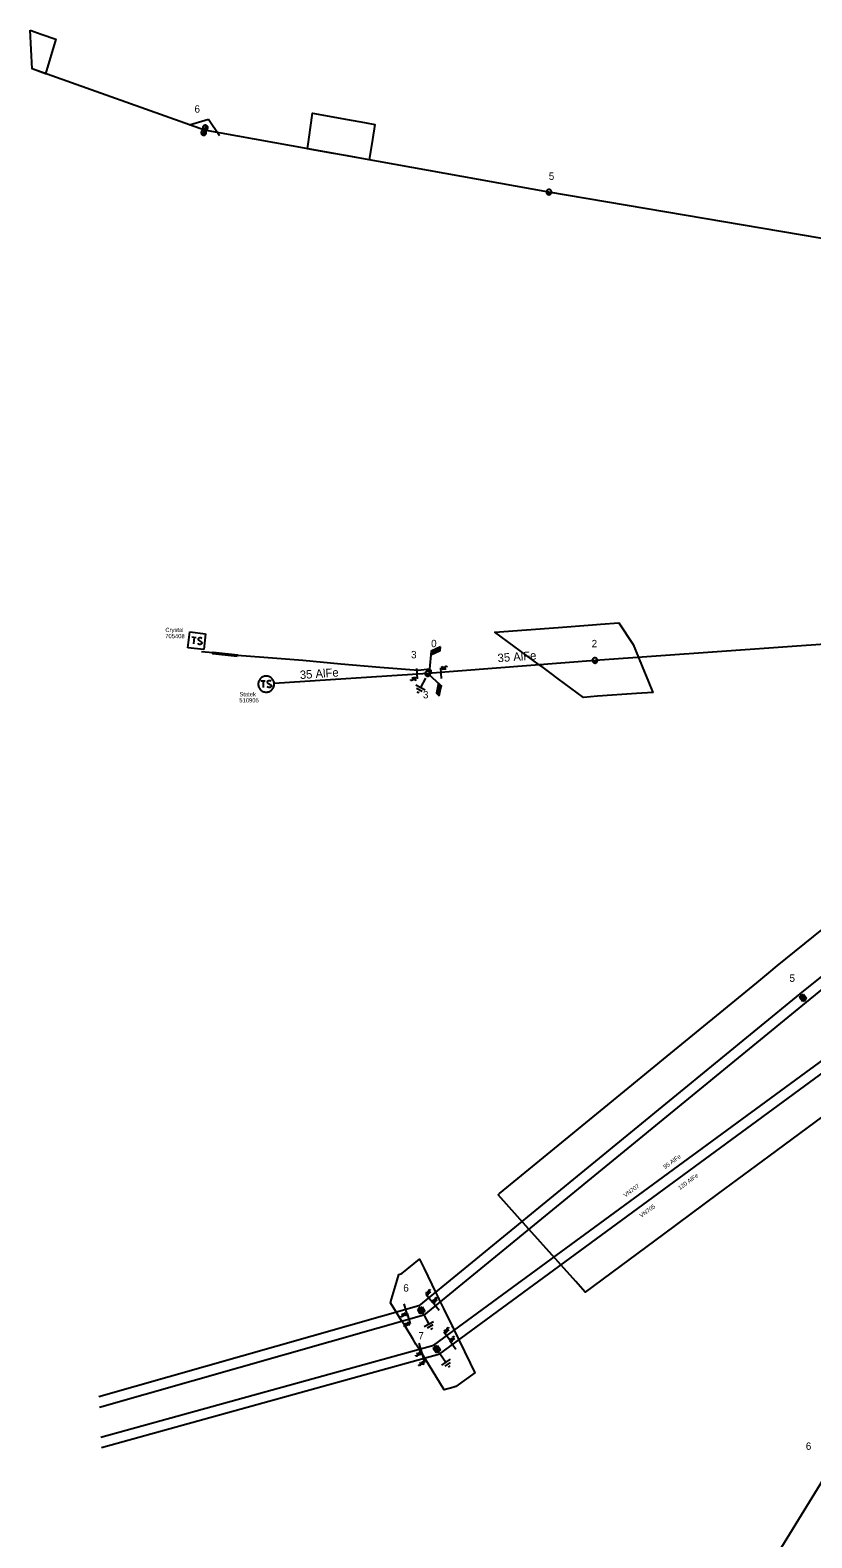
# Model space of a CAD drawing. Extents: x -545588 to -543214, y -1196037 to -1194452.
# Drawn here: x -545587.8 to -545402.3, y -1195194.1 to -1194836.6 of the extents above; entities that cross this region are included whole.
import ezdxf

# ---------------------------------------------------------------- set-up
doc = ezdxf.new("R2010")
doc.units = 0
for name, color, linetype in [('DOPLŇ_POPISY', 7, 'Continuous'), ('ELE_EON', 7, 'Continuous'), ('ELE_EON_POPIS', 7, 'Continuous'), ('Implicitní', 7, 'Continuous'), ('KONEC_VEDENÍ', 7, 'Continuous'), ('POL_ZNAČKA_PRACOVNÍ', 7, 'Continuous'), ('SDEL_EON', 7, 'Continuous'), ('TECH_OCHR_PÁSMO_HRAN', 7, 'Continuous'), ('Vrstva 18', 7, 'Continuous'), ('Vrstva 20', 7, 'Continuous'), ('Vrstva 25', 7, 'Continuous'), ('Vrstva 26', 7, 'Continuous'), ('Vrstva 27', 7, 'Continuous'), ('Vrstva 35', 7, 'Continuous'), ('Vrstva 52', 7, 'Continuous'), ('Vrstva 53', 7, 'Continuous'), ('ZP_EON', 7, 'Continuous'), ('ZP_EON_POPIS', 7, 'Continuous')]:
    doc.layers.add(name, color=color, linetype=linetype)

# ---------------------------------------------------------------- blocks, each defined once
blk = doc.blocks.new('VN840')
at = {"layer": 'POL_ZNAČKA_PRACOVNÍ'}
for points in [[(-0.01, 1.41), (-0.01, -1.09)], [(-1.51, -1.24), (-1.51, -1.15)], [(-1.48, -1.35), (-1.51, -1.24)], [(-1.33, -1.42), (-1.48, -1.35)], [(-1.27, -1.42), (-1.33, -1.42)], [(-1.13, -1.35), (-1.27, -1.42)], [(-1.09, -1.24), (-1.13, -1.35)], [(-1.09, -0.59), (-1.09, -1.24)], [(-0.68, -0.59), (-0.68, -1.42)], [(-0.68, -1.11), (-0.27, -0.59)], [(-0.54, -0.94), (-0.2, -1.42)]]:
    blk.add_lwpolyline(points, dxfattribs=at)
blk = doc.blocks.new('VN860')
at = {"layer": 'POL_ZNAČKA_PRACOVNÍ'}
for points in [[(-3.74, 0), (0.01, 2.82)], [(0.01, 2.82), (3.76, 0)]]:
    blk.add_lwpolyline(points, dxfattribs=at)
blk = doc.blocks.new('VN440')
at = {"layer": 'ELE_EON_POPIS'}
for points in [[(1.22, 0), (1.21, 0.13), (1.19, 0.25), (1.16, 0.38), (1.11, 0.5), (1.05, 0.61), (0.98, 0.72), (0.9, 0.82), (0.81, 0.91), (0.71, 0.99), (0.6, 1.06), (0.49, 1.12), (0.37, 1.16), (0.25, 1.2), (0.12, 1.22), (-0.01, 1.22), (-0.14, 1.22), (-0.26, 1.2), (-0.39, 1.16), (-0.51, 1.12), (-0.62, 1.06), (-0.73, 0.99), (-0.83, 0.91), (-0.92, 0.82), (-1, 0.72), (-1.07, 0.61), (-1.13, 0.5), (-1.18, 0.38), (-1.21, 0.25), (-1.23, 0.13), (-1.24, 0), (-1.23, -0.13), (-1.21, -0.26), (-1.18, -0.38), (-1.13, -0.5), (-1.07, -0.62), (-1, -0.73), (-0.92, -0.83), (-0.83, -0.92), (-0.73, -1), (-0.62, -1.07), (-0.51, -1.13), (-0.39, -1.17), (-0.26, -1.2), (-0.14, -1.23), (-0.01, -1.23), (0.12, -1.23), (0.25, -1.2), (0.37, -1.17), (0.49, -1.13), (0.6, -1.07), (0.71, -1), (0.81, -0.92), (0.9, -0.83), (0.98, -0.73), (1.05, -0.62), (1.11, -0.5), (1.16, -0.38), (1.19, -0.26), (1.21, -0.13), (1.22, 0)], [(-1.24, 0), (1.22, 0)], [(-1.18, -0.34), (1.1, -0.34)], [(-1.01, -0.63), (0.97, -0.63)], [(-0.74, -0.92), (0.68, -0.92)]]:
    blk.add_lwpolyline(points, dxfattribs=at)
blk = doc.blocks.new('VN810')
at = {"layer": 'POL_ZNAČKA_PRACOVNÍ'}
for points in [[(0, -1.25), (0, -3.75)], [(1.25, -3.75), (-1.25, -3.75)], [(0.77, -4.37), (-0.8, -4.37)], [(0, -5), (-0.25, -5)], [(0.27, -5), (0, -5)]]:
    blk.add_lwpolyline(points, dxfattribs=at)
blk = doc.blocks.new('VN640')
at = {"layer": 'ZP_EON_POPIS'}
for points in [[(-1.89, 1.89), (1.89, 1.89)], [(-1.89, -1.89), (-1.89, 1.89)], [(-1.26, 0.79), (-0.22, 0.79)], [(-0.73, 0.79), (-0.73, -0.79)], [(1.2, 0.66), (0.94, 0.79), (0.66, 0.79), (0.41, 0.66), (0.28, 0.47), (0.28, 0.41), (0.41, 0.22), (1.13, -0.16), (1.26, -0.32), (1.26, -0.47), (1.13, -0.66), (0.91, -0.79), (0.63, -0.79), (0.5, -0.73), (0.28, -0.6)], [(1.89, 1.89), (1.89, -1.89)], [(1.89, -1.89), (-1.89, -1.89)]]:
    blk.add_lwpolyline(points, dxfattribs=at)
blk = doc.blocks.new('VN610')
at = {"layer": 'ZP_EON_POPIS'}
for points in [[(1.88, 0), (1.87, 0.2), (1.84, 0.39), (1.79, 0.58), (1.72, 0.77), (1.63, 0.94), (1.52, 1.11), (1.4, 1.26), (1.26, 1.4), (1.1, 1.53), (0.94, 1.63), (0.76, 1.72), (0.58, 1.8), (0.39, 1.85), (0.19, 1.88), (-0.01, 1.89), (-0.21, 1.88), (-0.4, 1.85), (-0.59, 1.8), (-0.78, 1.72), (-0.95, 1.63), (-1.12, 1.53), (-1.27, 1.4), (-1.41, 1.26), (-1.54, 1.11), (-1.64, 0.94), (-1.73, 0.77), (-1.8, 0.58), (-1.86, 0.39), (-1.89, 0.2), (-1.9, 0), (-1.89, -0.2), (-1.86, -0.39), (-1.8, -0.58), (-1.73, -0.77), (-1.64, -0.95), (-1.54, -1.11), (-1.41, -1.27), (-1.27, -1.41), (-1.12, -1.53), (-0.95, -1.64), (-0.78, -1.73), (-0.59, -1.8), (-0.4, -1.85), (-0.21, -1.88), (-0.01, -1.89), (0.19, -1.88), (0.39, -1.85), (0.58, -1.8), (0.76, -1.73), (0.94, -1.64), (1.1, -1.53), (1.26, -1.41), (1.4, -1.27), (1.52, -1.11), (1.63, -0.95), (1.72, -0.77), (1.79, -0.58), (1.84, -0.39), (1.87, -0.2), (1.88, 0)], [(-1.27, 0.78), (-0.26, 0.78)], [(-0.76, 0.78), (-0.76, -0.79)], [(1.19, 0.66), (0.94, 0.78), (0.62, 0.78), (0.37, 0.66), (0.24, 0.47), (0.24, 0.4), (0.37, 0.22), (1.12, -0.16), (1.25, -0.32), (1.25, -0.48), (1.12, -0.67), (0.87, -0.79), (0.62, -0.79), (0.49, -0.73), (0.24, -0.6)]]:
    blk.add_lwpolyline(points, dxfattribs=at)
blk = doc.blocks.new('VN450')
at = {"layer": 'ELE_EON_POPIS'}
for points in [[(0, 0), (-0.01, 0.13), (-0.03, 0.25), (-0.06, 0.38), (-0.11, 0.5), (-0.16, 0.61), (-0.23, 0.72), (-0.31, 0.82), (-0.4, 0.91), (-0.5, 0.99), (-0.61, 1.06), (-0.72, 1.11), (-0.84, 1.16), (-0.97, 1.19), (-1.09, 1.21), (-1.22, 1.22), (-1.35, 1.21), (-1.47, 1.19), (-1.59, 1.16), (-1.71, 1.11), (-1.83, 1.06), (-1.93, 0.99), (-2.03, 0.91), (-2.12, 0.82), (-2.2, 0.72), (-2.27, 0.61), (-2.33, 0.5), (-2.38, 0.38), (-2.41, 0.25), (-2.43, 0.13), (-2.44, 0), (-2.43, -0.13), (-2.41, -0.25), (-2.38, -0.38), (-2.33, -0.5), (-2.27, -0.61), (-2.2, -0.72), (-2.12, -0.82), (-2.03, -0.91), (-1.93, -0.99), (-1.83, -1.06), (-1.71, -1.11), (-1.59, -1.16), (-1.47, -1.19), (-1.35, -1.21), (-1.22, -1.22), (-1.09, -1.21), (-0.97, -1.19), (-0.84, -1.16), (-0.72, -1.11), (-0.61, -1.06), (-0.5, -0.99), (-0.4, -0.91), (-0.31, -0.82), (-0.23, -0.72), (-0.16, -0.61), (-0.11, -0.5), (-0.06, -0.38), (-0.03, -0.25), (-0.01, -0.13), (0, 0)], [(-2.44, 0), (2.44, 0)], [(2.44, 0), (2.43, 0.13), (2.41, 0.25), (2.38, 0.38), (2.33, 0.5), (2.27, 0.61), (2.2, 0.72), (2.12, 0.82), (2.03, 0.91), (1.94, 0.99), (1.83, 1.06), (1.71, 1.11), (1.6, 1.16), (1.47, 1.19), (1.35, 1.21), (1.22, 1.22), (1.09, 1.21), (0.97, 1.19), (0.84, 1.16), (0.72, 1.11), (0.61, 1.06), (0.5, 0.99), (0.4, 0.91), (0.31, 0.82), (0.23, 0.72), (0.16, 0.61), (0.11, 0.5), (0.06, 0.38), (0.03, 0.25), (0.01, 0.13), (0, 0), (0.01, -0.13), (0.03, -0.25), (0.06, -0.38), (0.11, -0.5), (0.16, -0.61), (0.23, -0.72), (0.31, -0.82), (0.4, -0.91), (0.5, -0.99), (0.61, -1.06), (0.72, -1.11), (0.84, -1.16), (0.97, -1.19), (1.09, -1.21), (1.22, -1.22), (1.35, -1.21), (1.47, -1.19), (1.6, -1.16), (1.71, -1.11), (1.83, -1.06), (1.94, -0.99), (2.03, -0.91), (2.12, -0.82), (2.2, -0.72), (2.27, -0.61), (2.33, -0.5), (2.38, -0.38), (2.41, -0.25), (2.43, -0.13), (2.44, 0)], [(-2.4, -0.31), (-0.04, -0.31)], [(-2.26, -0.61), (-0.17, -0.61)], [(-2.01, -0.92), (-0.42, -0.92)], [(0.04, -0.31), (2.4, -0.31)], [(0.17, -0.61), (2.27, -0.61)], [(0.42, -0.92), (2.02, -0.92)]]:
    blk.add_lwpolyline(points, dxfattribs=at)
blk = doc.blocks.new('VN001')
at = {"layer": 'Implicitní'}
for p, q in [((2.05, 3.58), (4.46, 3.58)), ((2.07, 3.63), (4.49, 3.63)), ((2.1, 3.68), (4.52, 3.68)), ((2.13, 3.73), (2.54, 3.73)), ((1.73, 3.03), (4.14, 3.03)), ((1.76, 3.08), (4.17, 3.08)), ((1.79, 3.13), (4.2, 3.13)), ((1.82, 3.18), (4.23, 3.18)), ((1.85, 3.23), (4.26, 3.23)), ((1.87, 3.28), (4.29, 3.28)), ((1.9, 3.33), (4.32, 3.33)), ((1.93, 3.38), (4.35, 3.38)), ((1.96, 3.43), (4.37, 3.43)), ((1.99, 3.48), (4.4, 3.48)), ((2.02, 3.53), (4.43, 3.53))]:
    blk.add_line(p, q, dxfattribs=at)
blk.add_lwpolyline([(2.13, 3.73), (0, 0)], dxfattribs=at)
blk.add_lwpolyline([(4.55, 3.73), (2.13, 3.73), (1.7, 2.98), (4.12, 2.99)], close=True, dxfattribs=at)
blk = doc.blocks.new('VN470')
at = {"layer": 'ELE_EON_POPIS'}
for points in [[(-1.23, 1.22), (1.23, 1.22)], [(-1.23, -1.23), (-1.23, 1.22)], [(-0.92, 0.9), (0.92, 0.9)], [(-0.92, -0.95), (-0.92, 0.9)], [(-0.61, 0.61), (0.61, 0.61)], [(-0.61, -0.62), (-0.61, 0.61)], [(-0.31, -0.27), (-0.31, 0.34)], [(-0.31, 0.34), (0.31, 0.34)], [(0, 1.22), (0, 1.97)], [(0.31, 0.34), (0.31, -0.27)], [(0.61, 0.61), (0.61, -0.62)], [(0.92, 0.9), (0.92, -0.95)], [(1.23, 1.22), (1.23, -1.23)], [(1.23, -1.23), (-1.23, -1.23)], [(0.92, -0.95), (-0.92, -0.95)], [(0.61, -0.62), (-0.61, -0.62)], [(0.31, -0.27), (-0.31, -0.27)], [(0, -1.23), (0, -1.98)]]:
    blk.add_lwpolyline(points, dxfattribs=at)

msp = doc.modelspace()

# ---------------------------------------------------------------- linework, layer by layer
at = {"layer": 'ELE_EON'}
for points in [[(-545292.28, -1194904.3), (-545301.79, -1194902.92), (-545381.67, -1194889.04), (-545464.66, -1194874.97), (-545546.4, -1194860.3), (-545587.31, -1194845.75)], [(-545290.02, -1194972.8), (-545405.11, -1195065.07), (-545495.54, -1195139.14), (-545571.44, -1195160.65)], [(-545289.27, -1194973.82), (-545403.67, -1195067.08), (-545494.32, -1195141.28), (-545571.32, -1195163.18)], [(-545231.84, -1194976.41), (-545288.22, -1195044.64), (-545343.3, -1195111.41), (-545397.6, -1195177.04), (-545441.95, -1195249.1), (-545485.78, -1195319.69), (-545525.23, -1195383.69), (-545557.58, -1195435.71)], [(-545570.96, -1195170.23), (-545491.96, -1195148.44), (-545395.75, -1195077.92)], [(-545570.84, -1195172.71), (-545490.55, -1195150.49), (-545394.22, -1195079.84)]]:
    msp.add_lwpolyline(points, dxfattribs=at)
at = {"layer": 'Vrstva 20'}
msp.add_lwpolyline([(-545538.64, -1194985.08), (-545544.42, -1194984.46), (-545544.38, -1194984.06), (-545538.6, -1194984.68)], close=True, dxfattribs=at)
at = {"layer": 'Vrstva 35'}
for points in [[(-545587.77, -1194836.56), (-545587.5, -1194836.66), (-545586.88, -1194836.88), (-545585.14, -1194837.5), (-545581.71, -1194838.72), (-545584.09, -1194846.89), (-545587.31, -1194845.75)], [(-545515.8, -1194865.8), (-545521.97, -1194864.69), (-545521.65, -1194862.5), (-545520.74, -1194856.27), (-545512.5, -1194857.75), (-545508.47, -1194858.47), (-545505.98, -1194858.92), (-545506.56, -1194862.5), (-545507.34, -1194867.31), (-545512.5, -1194866.39)], [(-545467, -1194987.05), (-545477.51, -1194979.3), (-545462.5, -1194978.19), (-545454.35, -1194977.59), (-545452.46, -1194977.46), (-545448.12, -1194977.15), (-545444.69, -1194982.29), (-545443.44, -1194985.34), (-545442.55, -1194987.5), (-545441.08, -1194991.08), (-545440.03, -1194993.62), (-545443.89, -1194993.89), (-545453.13, -1194994.55), (-545456.49, -1194994.8), (-545462.5, -1194990.37), (-545464.15, -1194989.15), (-545466.39, -1194987.5)], [(-545487.5, -1195158.46), (-545489.5, -1195159.02), (-545494.16, -1195151.49), (-545494.91, -1195150.28), (-545495.45, -1195149.41), (-545496.22, -1195148.17), (-545496.96, -1195146.96), (-545498.82, -1195143.96), (-545499.56, -1195142.77), (-545500.11, -1195141.87), (-545500.87, -1195140.65), (-545502.27, -1195138.39), (-545502.01, -1195137.5), (-545501.09, -1195134.37), (-545500.3, -1195131.65), (-545499.56, -1195131.44), (-545495.37, -1195128.02), (-545494.28, -1195130.26), (-545491.55, -1195135.87), (-545490.93, -1195137.15), (-545490.76, -1195137.5), (-545490.46, -1195138.12), (-545489.83, -1195139.42), (-545489.7, -1195139.7), (-545487.73, -1195143.73), (-545487.5, -1195144.2), (-545487.15, -1195144.92), (-545486.64, -1195145.98), (-545486.05, -1195147.19), (-545483.38, -1195152.69), (-545482.27, -1195154.96), (-545486.78, -1195158.26)]]:
    msp.add_lwpolyline(points, close=True, dxfattribs=at)
msp.add_lwpolyline([(-545390.67, -1195087.5), (-545412.5, -1195103.63), (-545424.51, -1195112.5), (-545437.5, -1195122.1), (-545456.09, -1195135.83), (-545458.33, -1195133.33), (-545462.5, -1195128.68), (-545470.14, -1195120.14), (-545476.74, -1195112.78), (-545476.4, -1195112.5), (-545462.5, -1195101.11), (-545445.89, -1195087.5), (-545437.5, -1195080.63), (-545415.37, -1195062.5), (-545412.5, -1195060.15), (-545410.48, -1195058.49), (-545399.88, -1195049.88)], dxfattribs=at)
at = {"layer": 'Vrstva 52'}
for points in [[(-545295.62, -1194964.78), (-545381.37, -1194980.94), (-545453.74, -1194986.07), (-545493.42, -1194989.16)], [(-545493.42, -1194989.16), (-545529.88, -1194991.52)]]:
    msp.add_lwpolyline(points, dxfattribs=at)
at = {"layer": 'ZP_EON'}
msp.add_lwpolyline([(-545493.42, -1194989.16), (-545493.04, -1194989.14), (-545492.62, -1194988.9), (-545492.61, -1194988.44), (-545493.02, -1194988.11), (-545495.65, -1194988.42), (-545504.82, -1194987.68), (-545514.07, -1194986.91), (-545523.03, -1194986.02), (-545532.32, -1194985.33), (-545538.62, -1194984.88), (-545544.4, -1194984.26), (-545547.11, -1194984)], dxfattribs=at)

# ---------------------------------------------------------------- block references
at = {"layer": 'DOPLŇ_POPISY'}
for name, p, xscale, yscale, rotation in [('VN450', (-545546.4, -1194860.3), 0.5000000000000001, 0.5, 72.48316394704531), ('VN440', (-545464.66, -1194874.97), 0.49999999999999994, 0.5000000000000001, -10.174947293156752), ('VN440', (-545453.74, -1194986.04), 0.5000000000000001, 0.5, 4.213244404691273), ('VN440', (-545493.42, -1194989.16), 0.5, 0.5, 4.498162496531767), ('VN470', (-545404.4, -1195066.03), 0.5, 0.5, 35.95226383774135), ('VN470', (-545494.98, -1195140.18), 0.5, 0.5, 28.75484165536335), ('VN470', (-545491.27, -1195149.4), 0.49999999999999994, 0.5000000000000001, 35.22301664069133)]:
    msp.add_blockref(name, p, dxfattribs=dict(at, xscale=xscale, yscale=yscale, rotation=rotation))
at = {"layer": 'POL_ZNAČKA_PRACOVNÍ'}
for p, rotation in [((-545493.42, -1194989.16), -27.10344678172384), ((-545494.98, -1195140.18), 28.729269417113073), ((-545491.27, -1195149.4), 35.22301664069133)]:
    msp.add_blockref('VN810', p, dxfattribs=dict(at, rotation=rotation))
at = {"layer": 'TECH_OCHR_PÁSMO_HRAN'}
for p, rotation in [((-545493.02, -1194988.11), 24.089150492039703), ((-545493.42, -1194989.16), -102.34557422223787)]:
    msp.add_blockref('VN001', p, dxfattribs=dict(at, rotation=rotation))
at = {"layer": 'Vrstva 18'}
for name, p, rotation in [('VN860', (-545546.4, -1194860.3), -19.579736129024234), ('VN840', (-545496.03, -1194989.33), 3.702913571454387), ('VN840', (-545490.28, -1194988.91), -175.50424709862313), ('VN840', (-545493.21, -1195137.23), -140.68283054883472), ('VN840', (-545491.64, -1195139.09), -140.7008556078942), ('VN840', (-545498.67, -1195140.02), 15.82240275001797), ('VN840', (-545497.88, -1195142.29), 15.874486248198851), ('VN840', (-545488.94, -1195146.23), -143.75576663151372), ('VN840', (-545495.14, -1195149.32), 15.418513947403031), ('VN840', (-545487.58, -1195148.31), -143.74327498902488), ('VN840', (-545494.45, -1195151.57), 15.474536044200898)]:
    msp.add_blockref(name, p, dxfattribs=dict(at, rotation=rotation))
at = {"layer": 'Vrstva 25'}
for name, p, rotation in [('VN640', (-545548.23, -1194981.38), -6.719183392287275), ('VN610', (-545531.75, -1194991.65), 0.014666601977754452)]:
    msp.add_blockref(name, p, dxfattribs=dict(at, rotation=rotation))

# ---------------------------------------------------------------- texts
at = {"layer": 'ELE_EON_POPIS'}
for s, rotation, p in [('95 AlFe', 36.244, (-545437.09, -1195106.68)), ('120 AlFe', 36.257, (-545433.58, -1195111.68))]:
    msp.add_text(s, height=1, rotation=rotation, dxfattribs=at).set_placement(p)
at = {"layer": 'KONEC_VEDENÍ'}
for s, p in [('0', (-545492.62, -1194982.9)), ('3', (-545494.57, -1194995.04))]:
    msp.add_text(s, height=1.75, dxfattribs=at).set_placement(p)
at = {"layer": 'POL_ZNAČKA_PRACOVNÍ'}
for s, p in [('6', (-545548.77, -1194856.14)), ('5', (-545464.71, -1194872.07)), ('2', (-545454.54, -1194982.92)), ('3', (-545497.39, -1194985.53)), ('5', (-545407.59, -1195062.26)), ('6', (-545499.23, -1195135.73)), ('7', (-545495.66, -1195147.07)), ('6', (-545403.72, -1195173.25))]:
    msp.add_text(s, height=1.75, dxfattribs=at).set_placement(p)
at = {"layer": 'SDEL_EON'}
for s, rotation, p in [('VN707', 36.244, (-545446.51, -1195113.41)), ('VN705', 36.257, (-545442.72, -1195118.24))]:
    msp.add_text(s, height=1, rotation=rotation, dxfattribs=at).set_placement(p)
at = {"layer": 'Vrstva 26'}
msp.add_text('705408', height=1, dxfattribs=at).set_placement((-545555.72, -1194980.77))
msp.add_text('510905', height=1, rotation=0.015, dxfattribs=at).set_placement((-545538.13, -1194995.99))
at = {"layer": 'Vrstva 27'}
for s, p in [('Crystal', (-545555.69, -1194979.3)), ('Statek', (-545538.11, -1194994.55))]:
    msp.add_text(s, height=1, dxfattribs=at).set_placement(p)
at = {"layer": 'Vrstva 53'}
for rotation, p in [(4.213, (-545476.78, -1194986.48)), (3.965, (-545523.71, -1194990.47))]:
    msp.add_text('35 AlFe', height=2, rotation=rotation, dxfattribs=at).set_placement(p)

doc.saveas('drawing.dxf')
